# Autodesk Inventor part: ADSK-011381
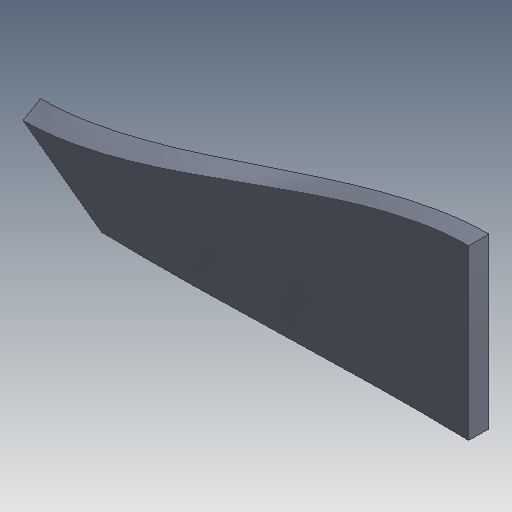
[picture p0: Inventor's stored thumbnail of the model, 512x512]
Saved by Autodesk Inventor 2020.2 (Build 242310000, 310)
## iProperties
Created: 2000-02
Part Number: ADSK-011381
Material: Pearson Stainless Steel
Document SubType Name: Modeling
Designer: gpurviance
Density: 8.03 g/cm^3
Appearance: Metal-Steel(Polish)
Mass: 31.4779 g
Surface Area: 31.1792 cm^2
Volume: 3.92004 cm^3
Control State: 0
Checked Out: False
Master: False
Shininess: 57.0
Length Units: 11272
Angle Units: 11279
Time Units: 11290
Mass Units: 11286
Length Display Precision: 3
Angle Display Precision: 2
Compacted: True
Cutlength: * USE SCRAP FOR THIS
Material Desc: SHEET,S/S, 11 GA
Material_Number: A084638
Dimensions: 1x0,6x2,1 in
Mass: 0,069 lb
VLT_Material: Pearson Stainless Steel
Density: 8.03
Volumn: 4.164349815588755
Area: 31.388804730404612
PropertySet Name: Model Information
Author: gpurviance
Revision Number: -
Title: ADSK-011381
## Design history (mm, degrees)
derived "ADSK-011384.ipt"
node "FonctionRepérage2"
feature "Volumenkörper2::ADSK-011384.ipt" dims "d0" = 10
node "Volumenkörper2"
node "Solide1"
node "Corps solides"
node "Corps surfaciques"
